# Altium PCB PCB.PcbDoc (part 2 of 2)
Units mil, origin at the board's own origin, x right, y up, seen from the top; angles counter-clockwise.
Board outline 4000 x 1900 mil, 2 copper layers (Top Layer, Bottom Layer), stack 62 mil thick; 73 components, 38 nets, 157 pads, 24 vias.
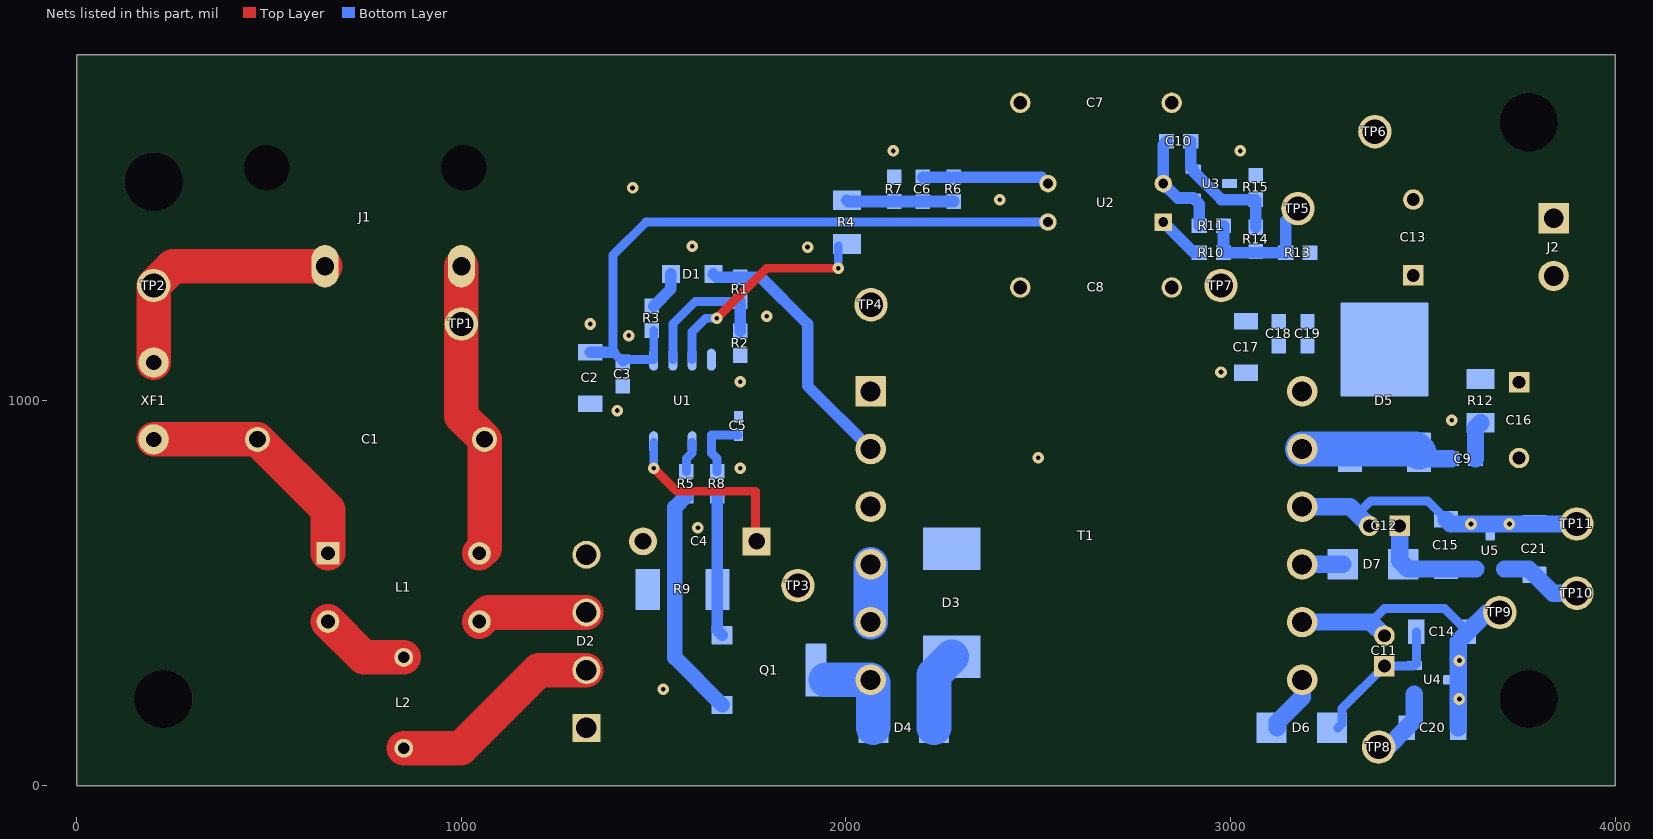
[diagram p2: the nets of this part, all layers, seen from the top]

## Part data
C1: library part CMP-0074799-2, "CAP, Film, 0.1 µF, X1 440 VAC, +/- 10%, AEC-Q200 Grade 1, TH", Cap_Case=18x11x19mm, Manufacturer=Kemet, Supplier Part Number 1=399-12721-ND, Tolerance_%=10%, Value2=1000V, ValueDisplayed=0.1µF
C2 C14 C15 C17 C20 C21: library part CMP-0085950-1, "CAP, CERM, 10 µF, 50 V,+/- 10%, X7R, AEC-Q200 Grade 1, 1206", Cap_Case=1206, Manufacturer=TDK, TempCo=X7R, Tolerance_%=10%, Value2=50V, ValueDisplayed=10µF
C3 C18 C19: library part CMP-0007039-5, "CAP, CERM, 0.1 uF, 25 V, +/- 10%, X7R, 0603", Cap_Case=0603, Manufacturer=TDK, Supplier Part Number 1=445-1316-1-ND, TempCo=X7R, Tolerance_%=10%, Value1=Unknown, Value2=25V, ValueDisplayed=0.1uF
C4: library part CMP-0010241-1, "CAP, AL, 47 uF, 400 V, +/- 20%, TH", Cap_Case="Radial  16x25mm", Manufacturer=Nichicon, Supplier Part Number 1=493-5877-ND, Tolerance_%=20%, Value1=Unknown, Value2=400V, ValueDisplayed=47uF
C5: library part CMP-0006687-2, "CAP, CERM, 330 pF, 50 V, +/- 10%, X7R, 0402", Cap_Case=0402, Manufacturer=MuRata, Supplier Part Number 1=490-3247-1-ND, TempCo=X7R, Tolerance_%=10%, Value1=Unknown, Value2=50V, ValueDisplayed=330pF
C6: library part CMP-0007423-4, "CAP, CERM, 0.047 uF, 25 V, +/- 10%, X7R, 0603", Cap_Case=0603, Manufacturer=MuRata, Supplier Part Number 1=490-1522-1-ND, TempCo=X7R, Tolerance_%=10%, Value1=Unknown, Value2=25V, ValueDisplayed=0.047uF
C7 C8: library part CMP-0086097-1, "CAP, CERM, 1000 pF, X1 760 VAC/Y1 500 VAC, +/- 20%, Y5U, 9x5mm", Cap_Case=9X5mm, Manufacturer=Vishay-Bccomponents, TempCo=Y5U, Tolerance_%=20%, ValueDisplayed=1000pF
C9: library part CMP-0007467-4, "CAP, CERM, 1000 pF, 100 V, +/- 10%, X7R, 0603", Cap_Case=0603, Manufacturer=MuRata, Supplier Part Number 1=490-1472-1-ND, TempCo=X7R, Tolerance_%=10%, Value1=Unknown, Value2=100V, ValueDisplayed=1000pF
C10: library part CMP-0007442-5, "CAP, CERM, 220 pF, 50 V, +/- 10%, X7R, 0603", Cap_Case=0603, Manufacturer=MuRata, Supplier Part Number 1=490-1483-1-ND, TempCo=X7R, Tolerance_%=10%, Value1=Unknown, Value2=50V, ValueDisplayed=220pF
C11 C12: library part CMP-0010335-1, "CAP, AL, 47 uF, 16 V, +/- 20%, 0.8 ohm, AEC-Q200 Grade 2, TH", Cap_Case=5x11mm, Manufacturer=Panasonic, Supplier Part Number 1=P11196-ND, Tolerance_%=20%, Value1="0.8 ohm", Value2=16V, ValueDisplayed=47uF
C13 C16: library part CMP-0010396-1, "CAP, AL, 470 uF, 16 V, +/- 20%, TH", Cap_Case=10x12.5, Manufacturer=Chemi-Con, Supplier Part Number 1=565-1660-ND, Tolerance_%=20%, Value1=Unknown, Value2=16V, ValueDisplayed=470uF
D1: library part CMP-0028782-2, "Diode, Schottky, 100 V, 1 A, AEC-Q101, SOD-123W", Manufacturer=Nexperia, Value1=1A, Value2=0.77V
D2: library part CMP-0029224-3, "Diode, Switching-Bridge, 600 V, 1.5 A, TH", Manufacturer="Diodes Inc.", Value1=1.5A, Value2=1.1V
D3: library part CMP-0065113-3, "Diode, TVS, Uni, 200 V, 324 Vc, SMC", Manufacturer=Littelfuse, Value1=1500W
D4: library part CMP-0076882-2, "Diode, Ultrafast, 1000 V, 1 A, SMA", Manufacturer="Diodes Inc.", Value1=1A, Value2=1.7V
D5: library part CMP-0077020-3, "Diode, Schottky, 200 V, 5 A, DPAK", Manufacturer="Diodes Inc.", Value1=5A, Value2=0.91V
D6 D7: library part CMP-0029024-2, "Diode, Ultrafast, 200 V, 1 A, SMA", Manufacturer="Diodes Inc.", Value1=1A, Value2=0.92V
H1 H2 H3 H4: library part CMP-0003686-1, Manufacturer=Keystone, Supplier Part Number 1=36-4826-ND
J1: library part CMP-0074930-1, "AC Receptacle, 2.5A, R/A, TH", Manufacturer="Qualtek Electronics Corporation", Supplier Part Number 1=Q273-ND
J2: library part CMP-0054822-2, "Terminal Block, 2x1, 3.81mm, 24-16 AWG, 10A, 300VAC, TH", Manufacturer="Wurth Elektronik"
L1: library part CMP-0084275-1, "Coupled inductor, 5 mH, 0.22 ohm, TH", Manufacturer="Wurth Elektronik", ValueDisplayed=5mH
L2: library part CMP-0064732-2, "Inductor, Toroid, Powdered Iron, 140 uH, 1 A, 0.11 ohm, TH", Manufacturer="Wurth Elektronik", Value1="0.11 ohm", Value2=1A, ValueDisplayed=140uH
Logo1: library part CMP-0074835-1, "IEC 61010-1 High Voltage Warning"
Logo2: library part CMP-0074847-1, "FCC_disclaimer"
Logo3: library part CMP-0074769-1
Q1: library part CMP-0750130-1, "MOSFET, N-CH, 700 V, 12.5 A, PG-SOT223", Alternate Manufacturer=None, Manufacturer="Infineon Technologies", Value1="? ohm", Value2="16.4 nC"
R1: library part CMP-0022439-4, "RES, 47.5 k, 1%, 0.1 W, AEC-Q200 Grade 0, 0603", Manufacturer=Vishay-Dale, Power_W=100mW, Supplier Part Number 1=541-47.5KHCT-ND, TempCo="100 ppm/C", Tolerance_%=1%, Value2=0.1W, Value_Code=47k5, ValueDisplayed=47.5k
R2: library part CMP-0022261-4, "RES, 28.7 k, 1%, 0.1 W, AEC-Q200 Grade 0, 0603", Manufacturer=Vishay-Dale, Power_W=100mW, Supplier Part Number 1=541-28.7KHCT-ND, TempCo="100 ppm/C", Tolerance_%=1%, Value2=0.1W, Value_Code=28k7, ValueDisplayed=28.7k
R3: library part CMP-0025743-4, "RES, 1.0, 5%, 0.1 W, AEC-Q200 Grade 0, 0603", Manufacturer=Vishay-Dale, Power_W=100mW, Supplier Part Number 1=541-1.0GCT-ND, TempCo="200 ppm/C", Tolerance_%=5%, Value2=0.1W, Value_Code=1R00, ValueDisplayed=1.0
R4: library part CMP-0018573-3, "RES, 0, 5%, 0.25 W, AEC-Q200 Grade 0, 1206", Manufacturer=Vishay-Dale, Power_W=250mW, Supplier Part Number 1=541-0.0ECT-ND, TempCo="200 ppm/C", Tolerance_%=5%, Value2=0.25W, Value_Code=0000, ValueDisplayed=0
R5: library part CMP-0025703-4, "RES, 10, 5%, 0.1 W, AEC-Q200 Grade 0, 0603", Manufacturer=Vishay-Dale, Power_W=100mW, Supplier Part Number 1=541-10GCT-ND, TempCo="200 ppm/C", Tolerance_%=5%, Value2=0.1W, Value_Code=10R0, ValueDisplayed=10
R6: library part CMP-0021990-4, "RES, 100 k, 1%, 0.1 W, AEC-Q200 Grade 0, 0603", Manufacturer=Vishay-Dale, Power_W=100mW, Supplier Part Number 1=541-100KHCT-ND, TempCo="100 ppm/C", Tolerance_%=1%, Value2=0.1W, Value_Code=100k
R7: library part CMP-0022220-4, "RES, 22.1 k, 1%, 0.1 W, AEC-Q200 Grade 0, 0603", Manufacturer=Vishay-Dale, Power_W=100mW, Supplier Part Number 1=541-22.1KHCT-ND, TempCo="100 ppm/C", Tolerance_%=1%, Value2=0.1W, Value_Code=22k1, ValueDisplayed=22.1k
R8: library part CMP-0022271-4, "RES, 2.15 k, 1%, 0.1 W, AEC-Q200 Grade 0, 0603", Manufacturer=Vishay-Dale, Power_W=100mW, Supplier Part Number 1=541-2.15KHCT-ND, TempCo="100 ppm/C", Tolerance_%=1%, Value2=0.1W, Value_Code=2k15, ValueDisplayed=2.15k
R9: library part CMP-0016531-2, "RES, 0.75, 1%, 1 W, 2010", Manufacturer="Stackpole Electronics Inc", Power_W=1W, Supplier Part Number 1=CSRN2010FKR750CT-ND, TempCo="250 ppm/C", Tolerance_%=1%, Value_Code=R750, ValueDisplayed=0.75
R10: library part CMP-0022126-4, "RES, 1.50 k, 1%, 0.1 W, AEC-Q200 Grade 0, 0603", Manufacturer=Vishay-Dale, Power_W=100mW, Supplier Part Number 1=541-1.50KHCT-ND, TempCo="100 ppm/C", Tolerance_%=1%, Value2=0.1W, Value_Code=1k50, ValueDisplayed=1.50k
R11: library part CMP-0021998-4, "RES, 10.0 k, 1%, 0.1 W, AEC-Q200 Grade 0, 0603", Manufacturer=Vishay-Dale, Power_W=100mW, Supplier Part Number 1=541-10.0KHCT-ND, TempCo="100 ppm/C", Tolerance_%=1%, Value2=0.1W, Value_Code=10k0, ValueDisplayed=10.0k
R12: library part CMP-0018625-3, "RES, 200, 5%, 0.25 W, AEC-Q200 Grade 0, 1206", Manufacturer=Vishay-Dale, Power_W=250mW, Supplier Part Number 1=541-200ECT-ND, TempCo="200 ppm/C", Tolerance_%=5%, Value2=0.25W, Value_Code=200R, ValueDisplayed=200
R13: library part CMP-0025697-4, "RES, 0, 5%, 0.1 W, AEC-Q200 Grade 0, 0603", Manufacturer=Vishay-Dale, Power_W=100mW, Supplier Part Number 1=541-0.0GCT-ND, TempCo="200 ppm/C", Tolerance_%=5%, Value2=0.1W, Value_Code=0000, ValueDisplayed=0
R14: library part CMP-0022649-3, "RES, 909 k, 1%, 0.1 W, AEC-Q200 Grade 0, 0603", Manufacturer=Vishay-Dale, Power_W=100mW, Supplier Part Number 1=541-909KHCT-ND, TempCo="100 ppm/C", Tolerance_%=1%, Value2=0.1W, Value_Code=909k
R15: library part CMP-0022087-4, "RES, 178 k, 1%, 0.1 W, AEC-Q200 Grade 0, 0603", Manufacturer=Vishay-Dale, Power_W=100mW, Supplier Part Number 1=541-178KHCT-ND, TempCo="100 ppm/C", Tolerance_%=1%, Value2=0.1W, Value_Code=178k
T1: library part CMP-0087102-1, "TRANSFORMER", Manufacturer="Wurth Electronics"
TP1: library part CMP-0055149-1, "Test Point, Multipurpose, White, TH", Color=White, Manufacturer=Keystone, Supplier Part Number 1=36-5012-ND
TP2: library part CMP-0055157-1, "Test Point, Multipurpose, Brown, TH", Color=Brown, Manufacturer=Keystone, Supplier Part Number 1=36-5125-ND
TP3 TP7 TP8 TP10: library part CMP-0055147-1, "Test Point, Multipurpose, Red, TH", Color=Red, Manufacturer=Keystone, Supplier Part Number 1=36-5010-ND
TP4 TP6 TP9 TP11: library part CMP-0055148-1, "Test Point, Multipurpose, Black, TH", Color=Black, Manufacturer=Keystone, Supplier Part Number 1=36-5011-ND
TP5: library part CMP-0055151-1, "Test Point, Multipurpose, Yellow, TH", Color=Yellow, Manufacturer=Keystone, Supplier Part Number 1=36-5014-ND
U1: library part CMP-0067231-2, "Constant-Voltage, Constant-Current PWM Controller with Primary-Side Regulation, D0007A (SOIC-7)", Alternate Manufacturer="Texas Instruments", Alternate PartNumber=UCC28711D
U2: library part CMP-0083653-1, "Optocoupler, 5.3 kV, 100-200% CTR, SMT", Manufacturer=Vishay-Semiconductor, Supplier Part Number 1=VO618A-3-ND, Voltage_Isolation_Vrms=5.3kV
U3: library part CMP-0066199-1, "2.5V Low Iq Adjustable Precision Shunt Regulator, DBZ0003A (SOT-23-3)", Alternate Manufacturer="Texas Instruments"
U4 U5: library part CMP-0074894-1, "100-mA, 30-V, Fixed-Output, Linear-Voltage Regulator, DBZ0003A (SOT-23-3)", Alternate Manufacturer="Texas Instruments", Alternate PartNumber=TLV76015DBZT
XF1: library part CMP-0003627-1, "Fuse Holder, TR5, TH", Manufacturer=Littelfuse, Supplier Part Number 1=WK6235-ND

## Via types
v1: diameter 29.92, hole 12.2, Top Layer to Bottom Layer, 24 vias

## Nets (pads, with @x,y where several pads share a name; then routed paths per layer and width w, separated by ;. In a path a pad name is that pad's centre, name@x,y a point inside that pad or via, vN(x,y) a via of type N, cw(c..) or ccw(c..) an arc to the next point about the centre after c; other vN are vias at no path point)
"AGND 1": C12.2 C15.2 C21.2 T1.10 TP11.1 U5.3 | length 804.4
  Bottom Layer w23: 3330,705.63 3364.37,740 3511.93,740 C15.2@3560,691.93
  Bottom Layer w45: T1.10@3186.03,725 3310.63,725 3330,705.63 C12.2@3360.63,675 ; C15.2@3560,691.93 3571.93,680 TP11.1@3900,680
  other v1: 3625,680 3725,680
"AGND 2": C11.2 C14.2 C20.2 T1.8 TP9.1 U4.3 | length 884.8
  Bottom Layer w23: 3364.37,425 3399.38,460 3556.93,460 C14.2@3616.93,400
  Bottom Layer w45: T1.8@3186.03,425 3364.37,425 C11.2@3400,389.37 ; C20.2@3591.93,150 3591.93,375 C14.2@3616.93,400 3666.93,450 TP9.1@3700,450
  other v1: 3595,225 3595,325
Bias: D1.2 R1.2 T1.2 | length 691.7
  Bottom Layer w30: D1.2@1655.12,1330 1663.62,1321.5 R1.2@1725,1321.5 1778.5,1321.5 1900,1200 1900,1038.98 T1.2@2063.98,875
NetC1_1: C1.1 L1.1 XF1.1 | length 642.1
  Top Layer w90: XF1.1@200,900 C1.1@469.72,900 653.15,716.57 L1.1@653.15,603.58
NetC1_2: C1.2 J1.1 L1.4 TP1.1 | length 777
  Top Layer w90: J1.1@1000,1350.08 TP1.1@1000,1200 1000,960.28 C1.2@1060.28,900 1060.28,617.01 L1.4@1046.85,603.58
NetC5_1: C5.1 R8.1 U1.5 | length 171.1
  Bottom Layer w23: R8.1@1665,816.5 1665,850 1650,865 U1.5@1650,892.72 1650,911.38 C5.1@1720,911.38
NetC6_1: C6.1 R6.2 U2.3 | length 331.8
  Bottom Layer w30: C6.1@2200,1581.5 2508.5,1581.5 U2.3@2525,1565
NetC6_2: C6.2 R4.1 R6.1 R7.2 | length 279
  Bottom Layer w30: R4.1@2002.5,1522.08 2006.08,1518.5 R6.1@2280,1518.5
NetC9_1: C9.1 R12.2 | length 98.5
  Bottom Layer w45: C9.1@3636.5,850 3636.5,929.41 R12.2@3650,942.91
NetC9_2: C9.2 D5.1 D5.3 T1.11 | length 397.8
  Bottom Layer w45: D5.1@3489.77,866.14 3505.91,850 C9.2@3573.51,850
  Bottom Layer w90: T1.11@3186.03,875 3480.91,875 D5.1@3489.77,866.14
NetC10_1: C10.1 R14.1 R15.2 U3.2 | length 345.4
  Bottom Layer w30: C10.1@2896.5,1675 2896.5,1608.66 U3.2@2902.76,1602.4 2902.76,1596.82 2976.07,1523.5 R15.2@3065,1523.5 R14.1@3065,1451.49
NetC10_2: C10.2 R11.1 U2.2 U3.1 | length 285.9
  Bottom Layer w30: C10.2@2833.51,1675 2825,1666.49 U2.2@2825,1565 2862.41,1527.59 U3.1@2902.76,1527.59 2918.51,1511.85 R11.1@2918.51,1455
NetC11_1: C11.1 C14.1 D6.1 U4.2 | length 379.1
  Bottom Layer w23: D6.1@3278.74,150 3290,161.26 3290,200.63 C11.1@3400,310.63 3475.98,310.63 U4.2@3477.76,312.4 3483.07,317.72 C14.1@3483.07,400
NetC12_1: C12.1 C15.1 D7.1 U5.2 | length 297.8
  Bottom Layer w45: C12.1@3439.37,675 3439.37,584.37 D7.1@3448.74,575 3460.98,562.76 U5.2@3637.6,562.76
NetC20_1: C20.1 TP8.1 U4.1 | length 194.5
  Bottom Layer w45: TP8.1@3380,100 3408.07,100 C20.1@3458.07,150 3477.76,169.68 U4.1@3477.76,237.6
NetC21_1: C21.1 TP10.1 U5.1 | length 213.6
  Bottom Layer w45: U5.1@3712.4,562.76 3775.31,562.76 C21.1@3790,548.07 3838.07,500 TP10.1@3900,500
NetD1_1: D1.1 R3.1 | length 102.1
  Bottom Layer w30: R3.1@1500,1246.5 1544.88,1291.38 D1.1@1544.88,1330
NetD2_2: D2.2 L2.2 | length 559.1
  Top Layer w90: L2.2@850,96.89 997.89,96.89 1201,300 D2.2@1325,300
NetD2_3: D2.3 L1.3 | length 287.9
  Top Layer w90: L1.3@1046.85,426.42 1070.43,450 D2.3@1325,450
NetD3_1: D3.1 D4.1 | length 203.7
  Bottom Layer w90: D4.1@2228.74,150 2228.74,288.25 D3.1@2275,334.51
NetD4_2: D4.2 Q1.2 T1.6 | length 244.9
  Bottom Layer w90: Q1.2@1947.05,275 T1.6@2063.98,275 2071.26,267.72 D4.2@2071.26,150
NetD6_2: D6.2 T1.7 | length 151.8
  Bottom Layer w45: D6.2@3121.26,150 3121.26,165 3186.03,229.77 T1.7@3186.03,275
NetD7_2: D7.2 T1.9 | length 105.2
  Bottom Layer w45: T1.9@3186.03,575 D7.2@3291.26,575
NetJ1_2: J1.2 TP2.1 XF1.2 | length 666.4
  Top Layer w90: XF1.2@200,1100 TP2.1@200,1300 250.08,1350.08 J1.2@645.67,1350.08
NetL1_2: L1.2 L2.1 | length 235.5
  Top Layer w90: L1.2@653.15,426.42 746.46,333.11 L2.1@850,333.11
NetQ1_1: Q1.1 R5.2 | length 607.4
  Bottom Layer w40: R5.2@1585,753.5 1555,723.5 1555,332.4 Q1.1@1677.95,209.45
NetQ1_3: Q1.3 R8.2 R9.2 | length 368.3
  Bottom Layer w30: R8.2@1665,753.5 1665,403.5 Q1.3@1677.95,390.55
NetR1_1: R1.1 R2.2 U1.2 | length 369
  Bottom Layer w23: U1.2@1550,1107.28 1550,1200 1608.5,1258.5 R1.1@1725,1258.5
  Bottom Layer w30: R2.2@1725,1181.5 R1.1@1725,1258.5
NetR4_2: R4.2 U1.3 | length 579
  Top Layer w23: v1(1663.62,1215) 1793.62,1345 v1(1980,1345)
  Bottom Layer w23: U1.3@1600,1107.28 1600,1180 1635,1215 v1(1663.62,1215) ; v1(1980,1345) R4.2@1980,1402.91
NetR5_1: R5.1 U1.6 | length 82.4
  Bottom Layer w23: R5.1@1585,816.5 1585,850 1600,865 U1.6@1600,892.72
NetR10_1: R10.1 U2.1 | length 126.6
  Bottom Layer w30: U2.1@2825,1465 2905,1385 R10.1@2918.51,1385
NetR10_2: R10.2 R11.2 R13.1 R14.2 TP5.1 | length 360.1
  Bottom Layer w30: R11.2@2981.5,1455 R10.2@2981.5,1385 R13.1@3143.51,1385 3143.51,1468.51 TP5.1@3175,1500
NetT1_4: T1.4 T1.5 | length 150
  Bottom Layer w90: T1.5@2063.98,425 T1.4@2063.98,575
PGND: C2.2 C3.1 C4.2 C5.2 C7.2 C8.2 D2.4 R2.1 R7.1 R9.1 T1.1 TP4.1 U1.4
  other v1: 1525,250 1615,670 1725,825 2500,852.01 1405,975 1725,1050 1435,1170 1335,1200 1793.62,1220 1900,1399.99 1600,1402.03 2400,1523.07 1445,1553.81 2122.88,1650
SGND: C7.1 C8.1 C13.2 C16.2 C17.2 C18.1 C19.1 J2.1 R15.1 T1.12 TP6.1 U3.3
  other v1: 3575,950 2975,1075 3025,1650
VBulk: C4.1 D2.1 D3.2 T1.3 TP3.1 U1.8 | length 488.7
  Top Layer w23: v1(1500,825) 1560,765 1765,765 1765,637.64 C4.1@1767.64,635
  Bottom Layer w23: v1(1500,825) U1.8@1500,892.72
VDD: C2.1 C3.2 R3.2 U1.1 U2.4 | length 1672.6
  Bottom Layer w23: R3.2@1500,1183.5 U1.1@1500,1107.28 1425.79,1107.28 C3.2@1420,1101.5 1394.57,1126.93 1394.57,1379.57 1480,1465 U2.4@2525,1465
  Bottom Layer w30: C2.1@1335,1126.93 1394.57,1126.93
Vout: C13.1 C16.1 C17.1 C18.2 C19.2 D5.2 J2.2 R12.1 R13.2 TP7.1
pads on no net: H1.0 H1.MH H2.0 H2.MH H3.0 H3.MH H4.0 H4.MH J1.MH1 J1.MH2

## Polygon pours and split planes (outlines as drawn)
"AGND 2" on Top Layer "TOP_LAYER_AGND_2_P018" (solid, remove dead copper, pour order 18): 3070,0 3070,370 3195,495 3750,495 3750,0
"AGND 1" on Top Layer "TOP_LAYER_AGND_1_P016" (solid, remove dead copper, pour order 16): 3135,545 3606.1,545 3745,545 4000,545 4000,735 3475,735 3430,780 3135,780
SGND on Top Layer "TOP_LAYER_SGND_P014" (solid, remove dead copper, pour order 14): 4000,1900 4000,800 3555.91,800 3480.91,875 3026.5,875 2800,1101.5 2800,1900
PGND on Top Layer "TOP_LAYER_PGND_P006" (solid, remove dead copper, pour order 6): 2550,1900 1250,1900 1250,600 1300,550 1375,550 1425,500 1425,200 1800,200 1800,795 2550,795
VBulk on Top Layer "TOP_LAYER_VBULK_P000" (solid, remove dead copper, pour order 0): 1250,0 1250,150 1300,200 1615,200 1725,310 1725,775 2450,775 2450,0
SGND on Bottom Layer "BOTTOM_LAYER_SGND_P012" (solid, remove dead copper, pour order 12): 4000,1900 4000,800 3555.91,800 3480.91,875 3026.5,875 2800,1101.5 2800,1900
Vout on Bottom Layer "BOTTOM_LAYER_VOUT_P010" (solid, remove dead copper, pour order 10): 3900,1410 2930,1410 2930,1333.5 2930,1250 3005,1175 3260,1175 3285,1150 3285,1010 3900,1010
PGND on Bottom Layer "BOTTOM_LAYER_PGND_P008" (solid, remove dead copper, pour order 8): 1250,1900 2550,1900 2550,0 1380,0 1380,200 1425,245 1425,500 1375,550 1300,550 1250,600
no net on Bottom Layer "BOTTOM_LAYER_NONET_P004" (solid, remove dead copper, pour order 4): 1725,1258.5
VBulk on Bottom Layer "BOTTOM_LAYER_VBULK_P002" (solid, remove dead copper, pour order 2): 2450,775 1725,775 1725,335 2450,335

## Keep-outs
Keep-Out Layer:
  text ".Layer_Name" at 577,-858.49 h60

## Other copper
Top Layer:
  text ".Layer_Name" at 577,-858.49 h60
Bottom Layer:
  text ".Layer_Name" at 577,-858.49 h60

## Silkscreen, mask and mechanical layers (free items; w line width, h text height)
Top Overlay:
  text "'.PRJ_Number'.PCB_Rev" at 1350,1780 h108.27
  text ".Layer_Name" at 577,-858.49 h60
Bottom Overlay:
  lines w10: 1395,780 1450,780 1450,850 1395,850 1395,780 ; 2950,1685 2950,1740 3020,1740 3020,1685 2950,1685 ; 3365,185 3365,255 3420,255 3420,185 3365,185 ; 3650,715 3650,785 3705,785 3705,715 3650,715
  text ".Layer_Name" at 577,-858.49 h60
Top Paste:
  text ".Layer_Name" at 577,-858.49 h60
Bottom Paste:
  text ".Layer_Name" at 577,-858.49 h60
Top Solder:
  text ".Layer_Name" at 577,-858.49 h60
  text ".Layer_Name" at 577,-858.49 h60
Bottom Solder:
  text ".Layer_Name" at 577,-858.49 h60
Drill Guide:
  text ".Layer_Name" at 577,-858.49 h60
M1 Board Outline:
  the board outline again, w10
  text ".Layer_Name" at 577,-858.49 h60
M2 Board Dimensions:
  rectangle: 0,-275 125,-150
  rectangle: 125,-400 500,-275
  lines w7: 0,-275 1000,-275 ; 125,-400 125,-150 ; 250,-400 250,-150 ; 500,-400 500,-150 ; 750,-400 750,-150 ; 0,-400 1000,-400 1000,-150 0,-150 0,-400
  text ".Layer_Name" at 577,-858.49 h60
M3 3D STEP Top:
  text ".Layer_Name" at 577,-858.49 h60
M4 3D STEP Bottom:
  text ".Layer_Name" at 577,-858.49 h60
M5 Assembly Top:
  lines w10: -292,-930.17 6308,-930.17 ; -292,-726.83 6310,-726.83 ; -292,-523.5 -292,-1133.5 3713,-1133.5 6310,-1133.5 6310,-523.5 -291.5,-523.5 -291.5,-1133.5 1284,-1133.5 ; 2173,-1133.5 2173,-523.5 ; 3440,-726.83 3440,-523.5 ; 4280,-726.83 4280,-523.5 ; 4902,-1140 4902,-937.17
  text "COMPONENTS MARKED 'DNP' SHOULD NOT BE POPULATED." at 1153.5,-318.5 h60
  text "ASSEMBLY VARIANT:" at 1153,-434 h60
  text ".VariantName" at 2189,-434 h60
  text "PCB VIEWED FROM TOP SIDE" at -228.5,-655.67 h60
  text "BOARD #:" at 2248,-655.67 h60
  text ".PRJ_Number" at 2793.5,-655.67 h60
  text "REV:" at 3638,-655.67 h60
  text ".PCB_Rev" at 3929.5,-655.67 h60
  text "SVN REV:" at 4476,-655.67 h60
  text ".VersionControl_RevNumber" at 4982,-655.67 h60
  text "TID #:" at 2248,-859 h60
  text ".TID" at 2793.5,-859 h60
  text "PLOT NAME =" at -228.5,-1064.34 h60
  text ".plot_File_Name" at 577,-1064.34 h60
  text "GENERATED    :" at 2250,-1064.34 h60
  text ".Print_Date" at 3119.5,-1064.34 h60
  text ".Print_Time" at 3848.5,-1064.34 h60
  text "TEXAS INSTRUMENTS" at 5113,-1064.34 h60
M6 Assembly Bottom:
  lines w10: -292.5,-727.33 6309.5,-727.33 ; -290.5,-930.67 6309.5,-930.67 ; 1115.5,-1140.5 1115.5,-937.67 ; 1737.5,-727.33 1737.5,-524 ; 2577.5,-727.33 2577.5,-524 ; 3844.5,-1134 3844.5,-524 ; 4733.5,-1134 6309,-1134 6309,-524 -292.5,-524 -292.5,-1134 2304.5,-1134 6309.5,-1134 6309.5,-524
  text "COMPONENTS MARKED 'DNP' SHOULD NOT BE POPULATED." at 6102,-318 h60
  text ".VariantName" at 5058,-434 h60
  text "ASSEMBLY VARIANT:" at 6097,-434 h60
  text ".VersionControl_RevNumber" at 1035.5,-656.17 h60
  text "SVN REV:" at 1541.5,-656.17 h60
  text ".PCB_Rev" at 2088,-656.17 h60
  text "REV:" at 2379.5,-656.17 h60
  text ".PRJ_Number" at 3224,-656.17 h60
  text "BOARD #:" at 3769.5,-656.17 h60
  text "PCB VIEWED FROM BOTTOM SIDE" at 6246,-656.17 h60
  text ".TID" at 3224,-859.5 h60
  text "TID #:" at 3769.5,-859.5 h60
  text "TEXAS INSTRUMENTS" at 904.5,-1064.84 h60
  text ".Print_Time" at 2169,-1064.84 h60
  text ".Print_Date" at 2898,-1064.84 h60
  text "GENERATED    :" at 3767.5,-1064.84 h60
  text ".plot_File_Name" at 5440.5,-1064.84 h60
  text "PLOT NAME =" at 6246,-1064.84 h60
M9 Title Sheet:
  drawing of 57 lines, arcs and shapes, not listed
  text "1" at 739.84,8036.5 h70
  text "2" at 3235.5,8036.5 h70
  text "3" at 5724.84,8036.5 h70
  text "4" at 8231.51,8036.5 h70
  text "5" at 10730.5,8036.5 h70
  text "6" at 13235.5,8036.5 h70
  text "A" at -416.5,6893.5 h70
  text "A" at 14383.5,6893.5 h70
  text "B" at -416.5,4513.5 h70
  text "B" at 14383.5,4513.5 h70
  text "C" at -416.5,2138.5 h70
  text "C" at 14383.5,2138.5 h70
  text "PROJECT TITLE:" at 11343.5,277.5 h45
  text ".PRJ_Title" at 11393.5,144.17 h70
  text "DESIGNED FOR:" at 11343.5,-23.5 h45
  text ".PRJ_Customer" at 11393.5,-163.5 h70
  text "D" at -416.5,-231.5 h70
  text "D" at 14383.5,-231.5 h70
  text "FILE NAME:" at 11343.5,-323.5 h45
  text ".PCB_File_Name_No_Path" at 11393.5,-443.5 h70
  text "Texas Instruments (TI) and/or its licensors do not warrant the accuracy or completeness of this specification" at 6374,-605.34 h45
  text "ENGINEER:" at 11343.5,-613.5 h45
  text "LAYOUT BY:" at 12848.5,-613.5 h45
  text "or any information contained therein. TI and/or its licensors do not warrant that this design will meet" at 6329.01,-718 h45
  text ".PRJ_Engineer" at 11393.5,-768.49 h70
  text ".PCB_Layout" at 12899,-768.49 h70
  text "the specifications, will be suitable for your application or fit for any particular purpose, or will operate in" at 6329.01,-830.67 h45
  text ".Layer_Name" at 577,-858.49 h60
  text "ALTIUM DESIGNER VERSION:" at 12848.5,-923.5 h45
  text "an implementation. TI and/or its licensors do not warrant that the design is production worthy. You should" at 6329.01,-943.33 h45
  text "completely validate and test your design implementation to confirm the system functionality for your application." at 6374,-1056 h45
  text ".print_Scale" at 11393.5,-1056.83 h70
  text ".Application_BuildNumber" at 12899,-1056.83 h70
  text "1" at 739.84,-1263.5 h70
  text "2" at 3235.5,-1263.5 h70
  text "3" at 5724.84,-1263.5 h70
  text "4" at 8231.51,-1263.5 h70
  text "5" at 10730.5,-1263.5 h70
  text "6" at 13235.5,-1263.5 h70
M10 Fab Notes:
  drawing of 189 lines, arcs and shapes, not listed
  text "DESIGN INFORMATION" at 12382.02,6356.17 h60
  text "MIN. TRACK WIDTH:" at 11737.46,6224.05 h60
  text "8" at 12833.7,6224.05 h60
  text "MIL" at 12988.46,6224.05 h60
  text "MIN. CLEARANCE:" at 11737.46,6099.92 h60
  text "0.2" at 12773.7,6099.93 h60
  text "mm" at 12988.46,6099.92 h60
  text "MIN. VIA PAD SIZE:" at 11737.46,5975.8 h60
  text "24" at 12803.71,5975.8 h60
  text "MIL" at 12988.46,5975.8 h60
  text "0.05mm (2MIL)" at 12432.46,5845.9 h60
  text "MINIMUM ANNULAR RING" at 11408.23,5837.67 h60
  text "EXTERNAL" at 13140.46,5837.67 h60
  text "PER" at 11608.23,5727.55 h60
  text "IPC-D-275 CLASS 2 LEVEL C" at 11828.23,5727.54 h60
  text "MIL, HOLES" at 13316.46,5627.07 h60
  text "+/-" at 12924,5618.48 h60
  text "+/-" at 13778,5618.48 h60
  text "REGISTRATION TOLERANCES:" at 11408.23,5617.42 h60
  text "METAL" at 12608,5617.42 h60
  text "5" at 13184.2,5617.42 h60
  text "3" at 14017.2,5617.42 h60
  text "MIL" at 14133.46,5617.42 h60
  text "HOLE SIZE TOLERANCE (UNLESS OTHERWISE SPECIFIED):" at 11408.23,5519.1 h60
  text "+/-" at 13778,5516.23 h60
  text "3" at 14017.2,5515.17 h60
  text "MIL" at 14133.46,5515.17 h60
  text "MATERIAL:" at 11333.46,5377.52 h60
  text "FR-4 High Tg" at 12319.9,5249 h60
  text "X" at 12175.46,5241.01 h60
  text "FR-408" at 11754.46,5236.49 h60
  text "OTHER" at 13242.46,5236.49 h60
  text "62 MIL (1.6mm) +/-10%" at 12074.56,5093.46 h60
  text "X" at 11954.46,5091.01 h60
  text "THICKNESS:" at 11408.23,5085.24 h60
  text "OTHER" at 13359.46,5085.24 h60
  text "TOLERANCE:" at 11408.23,4946.92 h60
  text "X" at 12256.46,4946.92 h60
  text "ANSI IPC-6012 TYPE 3 CLASS 2" at 12434.48,4946.92 h60
  text "OTHER +/-" at 12434.46,4802.73 h60
  text "BOW & TWIST:" at 11408.23,4657.54 h60
  text "X" at 12256.46,4657.54 h60
  text "ANSI IPC-6012 TYPE 3 CLASS 2" at 12434.48,4657.54 h60
  text "OTHER +/-" at 12434.46,4510.85 h60
  text "DRILLING:" at 11333.46,4380.23 h60
  text "NC_DRILL FILES" at 13094.46,4275.04 h60
  text "REFERENCE:" at 11408.23,4271.1 h60
  text "X" at 12065.46,4271.01 h60
  text "AS SHOWN" at 12243.46,4271.1 h60
  text "X" at 12966.46,4271.1 h60
  text "OTHER" at 13392.46,4128.85 h60
  text "PTH COPPER THICKNESS:" at 11407.91,4125.32 h60
  text "X" at 12547.14,4125.32 h60
  text "20-30 um" at 12675.14,4125.32 h60
  text "BOARD FINISH:" at 11333.46,3977.73 h60
  text "SILKSCREEN:" at 11488.68,3867.6 h60
  text "X" at 12446.46,3867.6 h60
  text "TOP" at 12563.46,3867.6 h60
  text "X" at 12956.46,3867.6 h60
  text "BOTTOM" at 13074.46,3867.6 h60
  text "SILKSCREEN COLOR:" at 11488.68,3712.41 h60
  text "X" at 12445.46,3712.41 h60
  text "WHITE" at 12563.46,3712.41 h60
  text "OTHER" at 13074.46,3712.41 h60
  text "X" at 12576.46,3568.96 h60
  text "GREEN" at 12694.46,3568.96 h60
  text "OTHER" at 13312.46,3568.96 h60
  text "SOLDER RESIST COLOR:" at 11488.68,3562.1 h60
  text "X" at 12576.46,3414.71 h60
  text "MATTE" at 12694.46,3414.71 h60
  text "SEMI-GLOSS" at 13312,3414.07 h60
  text "IMMERSION GOLD (ENIG)" at 12394.46,3241.94 h60
  text "ENEPIG" at 13732,3234.72 h60
  text "SURFACE FINISH:" at 11333.46,3233.72 h60
  text "X" at 12216.46,3233.72 h60
  text "IMM. TIN/SILVER OR EQUIV" at 11663,3096.4 h60
  text "OTHER" at 13094.46,3092.47 h60
  text "ARRAY/PANEL:" at 11333.46,2937.09 h60
  text "CUT AND TRIM PER M1 BOARD OUTLINE" at 12394.46,2928.87 h60
  text "N.C. ROUTE" at 12394.46,2792.9 h60
  text "X" at 13082.46,2792.9 h60
  text "V. SCORE" at 13260.46,2792.9 h60
  text "CERTIFICATION:" at 11333.46,2663.77 h60
  text "MATERIALS AND WORKMANSHIP FOR ALL PCBS" at 12058.46,2663.77 h60
  text "TO MEET OR EXCEED THE REQUIREMENTS OF:" at 12058.46,2569.71 h60
  text "X" at 11695.97,2441.08 h60
  text "ANSI IPC-A-600F CLASS ->" at 11823.96,2441.08 h60
  text "X" at 13471.97,2441.08 h60
  text "2" at 13581.96,2441.08 h60
  text "1" at 13266.96,2439.58 h60
  text "3" at 13935.96,2439.58 h60
  text "X" at 12507.97,2293.39 h60
  text "RoHS" at 12635.96,2293.39 h60
  text "OTHER" at 13280.36,2293.39 h60
  text "PER ORDER" at 13677.42,2293.39 h60
  text "ALL BOARDS MUST MEET OR EXCEED UL94-V0 REQUIREMENTS." at 11361,2139.57 h60
  text "PCB MUST BEAR THE UL94V-0 UL REGISTERED MATERIAL ID NUMBER" at 11361,2023.5 h60
  text "ADDITIONAL REQUIREMENTS:" at 11333.46,1854.08 h60
  text "MICROSECTION:" at 11408.23,1746.95 h60
  text "YES" at 12313.96,1746.95 h60
  text "REQUIRED" at 13175.46,1602.62 h60
  text "BARE BOARD ELEC. TEST:" at 11408.23,1599.76 h60
  text "NONE" at 12713.96,1599.76 h60
  text "X" at 13057.46,1599.76 h60
  text "PER ORDER" at 13767.46,1599.76 h60
  text "XX MIL VIAS REQUIRE NON-CONDUCTIVE FILL AND PLANARIZE" at 11576.38,1394.82 h59
  text "XX MIL VIAS REQUIRE CONDUCTIVE FILL AND PLANARIZE" at 11584.38,1290.84 h60
  text "OUTER XX MIL TRACES REQUIRE 50 OHM SINGLE-ENDED IMPEDANCE" at 11583.39,1127.46 h58
  text "LAYER 2 & 3 (INNER LAYERS) XX MIL WIDE, XX MIL SPACE / TRACES REQUIRE 100 OHM DIFFERENTIAL IMPEDANCE" at 11575.39,891.74 h60
  text ".Layer_Name" at 577,-858.49 h60
M11 Gerber Information:
  lines w10: -292,-930.17 6308,-930.17 ; -292,-726.83 6310,-726.83 ; -292,-523.5 -292,-1133.5 3713,-1133.5 6310,-1133.5 6310,-523.5 -291.5,-523.5 -291.5,-1133.5 1284,-1133.5 ; 2173,-1133.5 2173,-523.5 ; 3440,-726.83 3440,-523.5 ; 4280,-726.83 4280,-523.5 ; 4902,-1140 4902,-937.17
  text "ALL ARTWORK VIEWED FROM TOP SIDE" at -228.5,-655.67 h60
  text "BOARD #:" at 2248,-655.67 h60
  text ".PRJ_Number" at 2793.5,-655.67 h60
  text "REV:" at 3638,-655.67 h60
  text ".PCB_Rev" at 3929.5,-655.67 h60
  text "SVN REV:" at 4476,-655.67 h60
  text ".VersionControl_RevNumber" at 4982,-655.67 h60
  text "LAYER NAME =" at -228.5,-858.49 h60
  text "TID #:" at 2248,-859 h60
  text ".TID" at 2793.5,-859 h60
  text "PLOT NAME =" at -228.5,-1064.34 h60
  text ".plot_File_Name" at 577,-1064.34 h60
  text "GENERATED    :" at 2250,-1064.34 h60
  text ".Print_Date" at 3119.5,-1064.34 h60
  text ".Print_Time" at 3848.5,-1064.34 h60
  text "TEXAS INSTRUMENTS" at 5113,-1064.34 h60
M12 Stackup:
  drawing of 191 lines, arcs and shapes, not listed
  text "Layer" at 9407.5,7572.5 h60
  text "Name" at 9817.41,7572.5 h60
  text "Material" at 10747.16,7572.5 h60
  text "Thickness" at 11606.92,7572.5 h60
  text "Constant" at 12256.76,7572.5 h60
  text "Board Layer Stack" at 12826.62,7572.5 h60
  text "1" at 9407.5,7452.5 h60
  text "Top Overlay" at 9817.41,7452.5 h60
  text "2" at 9407.5,7332.5 h60
  text "Top Solder" at 9817.41,7332.5 h60
  text "Solder Resist" at 10747.16,7332.5 h60
  text "0.40mil" at 11606.92,7332.5 h60
  text "3.5" at 12256.76,7332.5 h60
  text "3" at 9407.5,7212.5 h60
  text "Top Layer" at 9817.41,7212.5 h60
  text "Copper" at 10747.16,7212.5 h60
  text "1.40mil" at 11606.92,7212.5 h60
  text "4" at 9407.5,7092.5 h60
  text "Dielectric1" at 9817.41,7092.5 h60
  text "FR-4" at 10747.16,7092.5 h60
  text "59.20mil" at 11606.92,7092.5 h60
  text "4.8" at 12256.76,7092.5 h60
  text "5" at 9407.5,6972.5 h60
  text "Bottom Layer" at 9817.41,6972.5 h60
  text "Copper" at 10747.16,6972.5 h60
  text "1.40mil" at 11606.92,6972.5 h60
  text "6" at 9407.5,6852.5 h60
  text "Bottom Solder" at 9817.41,6852.5 h60
  text "Solder Resist" at 10747.16,6852.5 h60
  text "0.40mil" at 11606.92,6852.5 h60
  text "3.5" at 12256.76,6852.5 h60
  text "7" at 9407.5,6732.5 h60
  text "Bottom Overlay" at 9817.41,6732.5 h60
  text ".Layer_Name" at 577,-858.49 h60
M13 Component Bodies Top:
  text ".Layer_Name" at 577,-858.49 h60
M14 Component Bodies Bottom:
  text ".Layer_Name" at 577,-858.49 h60
M15 Courtyards Top:
  text ".Layer_Name" at 577,-858.49 h60
M16 Courtyards Bottom:
  text ".Layer_Name" at 577,-858.49 h60
Drill Drawing:
  drawing of 152 lines, arcs and shapes, not listed
  text "Symbol" at 835.59,4554.62 h72
  text "Quantity" at 1136.16,4554.62 h72
  text "Finished Hole Size" at 1468.16,4554.62 h72
  text "Plated" at 2104.72,4554.62 h72
  text "Hole Type" at 2363.86,4554.62 h72
  text "Drill Layer Pair" at 2739.02,4554.62 h72
  text "Hole Tolerance" at 3463.35,4554.62 h72
  text "2" at 1136.16,4430.3 h60
  text "118.11mil (3.000mm)" at 1468.16,4430.3 h60
  text "NPTH" at 2104.72,4430.3 h60
  text "Round" at 2363.86,4430.3 h60
  text "Top Layer - Bottom Layer" at 2739.02,4430.3 h60
  text "4" at 1136.16,4305.98 h60
  text "152.00mil (3.861mm)" at 1468.16,4305.98 h60
  text "NPTH" at 2104.72,4305.98 h60
  text "Round" at 2363.86,4305.98 h60
  text "Top Layer - Bottom Layer" at 2739.02,4305.98 h60
  text "24" at 1136.16,4181.66 h60
  text "12.21mil (0.310mm)" at 1468.16,4181.66 h60
  text "PTH" at 2104.72,4181.66 h60
  text "Round" at 2363.86,4181.66 h60
  text "Top Layer - Bottom Layer" at 2739.02,4181.66 h60
  text "4" at 1136.16,4057.34 h60
  text "25.59mil (0.650mm)" at 1468.16,4057.34 h60
  text "PTH" at 2104.72,4057.34 h60
  text "Round" at 2363.86,4057.34 h60
  text "Top Layer - Bottom Layer" at 2739.02,4057.34 h60
  text "2" at 1136.16,3933.02 h60
  text "29.53mil (0.750mm)" at 1468.16,3933.02 h60
  text "PTH" at 2104.72,3933.02 h60
  text "Round" at 2363.86,3933.02 h60
  text "Top Layer - Bottom Layer" at 2739.02,3933.02 h60
  text "8" at 1136.16,3808.7 h60
  text "33.47mil (0.850mm)" at 1468.16,3808.7 h60
  text "PTH" at 2104.72,3808.7 h60
  text "Round" at 2363.86,3808.7 h60
  text "Top Layer - Bottom Layer" at 2739.02,3808.7 h60
  text "8" at 1136.16,3684.38 h60
  text "35.43mil (0.900mm)" at 1468.16,3684.38 h60
  text "PTH" at 2104.72,3684.38 h60
  text "Round" at 2363.86,3684.38 h60
  text "Top Layer - Bottom Layer" at 2739.02,3684.38 h60
  text "2" at 1136.16,3560.06 h60
  text "39.37mil (1.000mm)" at 1468.16,3560.06 h60
  text "PTH" at 2104.72,3560.06 h60
  text "Round" at 2363.86,3560.06 h60
  text "Top Layer - Bottom Layer" at 2739.02,3560.06 h60
  text "4" at 1136.16,3435.74 h60
  text "43.31mil (1.100mm)" at 1468.16,3435.74 h60
  text "PTH" at 2104.72,3435.74 h60
  text "Round" at 2363.86,3435.74 h60
  text "Top Layer - Bottom Layer" at 2739.02,3435.74 h60
  text "2" at 1136.16,3311.42 h60
  text "51.18mil (1.300mm)" at 1468.16,3311.42 h60
  text "PTH" at 2104.72,3311.42 h60
  text "Round" at 2363.86,3311.42 h60
  text "Top Layer - Bottom Layer" at 2739.02,3311.42 h60
  text "12" at 1136.16,3187.1 h60
  text "51.97mil (1.320mm)" at 1468.16,3187.1 h60
  text "PTH" at 2104.72,3187.1 h60
  text "Round" at 2363.86,3187.1 h60
  text "Top Layer - Bottom Layer" at 2739.02,3187.1 h60
  text "4" at 1136.16,3062.78 h60
  text "53.15mil (1.350mm)" at 1468.16,3062.78 h60
  text "PTH" at 2104.72,3062.78 h60
  text "Round" at 2363.86,3062.78 h60
  text "Top Layer - Bottom Layer" at 2739.02,3062.78 h60
  text "11" at 1136.16,2938.46 h60
  text "63.00mil (1.600mm)" at 1468.16,2938.46 h60
  text "PTH" at 2104.72,2938.46 h60
  text "Round" at 2363.86,2938.46 h60
  text "Top Layer - Bottom Layer" at 2739.02,2938.46 h60
  text "2" at 1136.16,2814.14 h60
  text "47.24mil (1.200mm)" at 1468.16,2814.14 h60
  text "PTH" at 2104.72,2814.14 h60
  text "Slot" at 2363.86,2814.14 h60
  text "Top Layer - Bottom Layer" at 2739.02,2814.14 h60
  text "89 Total" at 1136.16,2689.82 h60
  text "Slot definitions :" at 835.59,2602.8 h60
  text "Routed Path Length" at 1286.31,2602.8 h60
  text "= Calculated from tool start centre position to tool end centre position." at 1826.05,2602.8 h60
  text "Hole Length" at 1286.31,2553.07 h60
  text "= Routed Path Length + Tool Size = Slot length as defined in the PCB layout" at 1626.24,2553.07 h60
  text ".Layer_Name" at 577,-858.49 h60
M17 Embedded Cavity:
  text ".Layer_Name" at 577,-858.49 h60
M18 Embedded Assembly:
  text ".Layer_Name" at 577,-858.49 h60
M19 Embedded Keepout:
  text ".Layer_Name" at 577,-858.49 h60

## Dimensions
0,-400 to 1000,-400 on M2 Board Dimensions
0,0 to 0,1900 on M2 Board Dimensions
0,0 to 4000,0 on M2 Board Dimensions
